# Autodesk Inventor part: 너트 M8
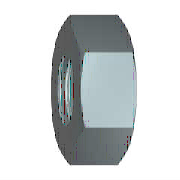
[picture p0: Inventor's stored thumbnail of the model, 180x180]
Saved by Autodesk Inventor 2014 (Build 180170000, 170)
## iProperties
IsCustomPart: 1
Created: 2012-02
Part Number: 너트 M8
Material: 강철, 연강
Description: 6각 너트
Document SubType Name: Modeling
Standard: KS B 1012
Designer: mduedu
Standards Organization: KS
Language: ko-KR
Size Designation: M8
Categories: <MemberInstance><Categories><Category DisplayName="조임쇠" InternalName="e4da775c-781d-43d5-af7c-5136215cf5a6" Mnemonic="FSTN"><Category DisplayName="너트" InternalN
Density: 1 g/cm^3
Appearance: Steel
Author: mduedu
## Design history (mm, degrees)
sketch "스케치1"
  geometry: L1 (-7.506, 0)-(-3.753, 6.5); L2 (-3.753, 6.5)-(3.753, 6.5); L3 (3.753, 6.5)-(7.506, 0); L4 (7.506, 0)-(3.753, -6.5); L5 (3.753, -6.5)-(-3.753, -6.5); L6 (-3.753, -6.5)-(-7.506, 0); 2 further points
  constraints: 12 end point, 1 coincident, 1 horizontal, 11 other
  dimensions: "d0" = 15.01111 distance of L3.end L1.start (= 1.1547 x SW)
extrude "본체" new body sketch "스케치1" distance "d1" = 5 (= KOH); taper "d2" = 0 deg
sketch "스케치2"
  geometry: L1 (0, 3.753)-(0, 7.506) reference; L2 (0, 7.506)-(5, 7.506) reference; L3 (5, 3.753)-(5, 7.506) reference; L4 (-1, 0)-(6, 0) reference; L5 (0.581, 7.506)-(0, 6.5); L6 (4.419, 7.506)-(5, 6.5)
  constraints: 4 end point, 4 point on line
  dimensions: "d3" = 30 deg angle of L1 L5 (= ANG1); "d4" = 30 deg angle of L3 L6 (= ANG2); "d5" = 13 diameter of L5.end L4 (= SW0); "d6" = 13 diameter of L6.end L4 (= SW01)
revolve "모따기1" sketch "스케치2" stored, may be unused: angle "d7" = 90 deg
sketch "스케치3"
  geometry: A1 r 6.5 centre (0, 0) between (-3.25, -5.629) and (3.25, -5.629) reference; 1 further point
  constraints: 1 coincident
hole "스레드" sketch "스케치3" at (0, 0) diameter "d25" = 6.647; stored, may be unused: countersink angle "d29" = 82 deg, drill point angle "d31" = 118 deg; dims "d26" = 6, "d27" = 4, "d28" = 2, "d30" = 8
workaxis "Work Axis1"
workplane "Work Plane1"
body "Solid1"
chamfer "모따기2" distance "d8" = 0.67658 (= -0.5 x GD1 + 0.5 x NND); stored, may be unused: angle "d9" = 30 deg, second distance "d40" = 0.67658 (= -0.5 x GD1 + 0.5 x NND)
chamfer "모따기3" distance "d10" = 0.67658 (= -0.5 x GD1 + 0.5 x NND); stored, may be unused: angle "d11" = 30 deg, second distance "d41" = 0.67658 (= -0.5 x GD1 + 0.5 x NND)
other parameters: "ANG1" = 30 deg [user parameter; used in 1 equation term], "ANG2" = 30 deg [user parameter; used in 1 equation term], "NND" = 8 [user parameter; used in 4 equation terms], "KOH" = 5 [user parameter; used in 1 equation term], "SW" = 13 [user parameter; used in 4 equation terms], "SW0" = 13 (= SW) [user parameter; used in 1 equation term], "SW01" = 13 (= SW) [user parameter; used in 1 equation term], "GD1" = 6.64684 (computed from THREADDIA, PTC, TOA) [user parameter; used in 4 equation terms], "d13" = 0, "d14" = 0, "d39" = 0, "d42" = 0, "GUL" = 0.67658 (= 0.541266 x PTC) [user parameter], "TPU" = 8 (computed from PTC) [user parameter], "THREADDIA" = 8 [user parameter; used in 1 equation term], "TOA" = 30 deg [user parameter; used in 1 equation term], "PTC" = 1.25 [user parameter; used in 4 equation terms], "E0" = 15.015 (= 1.155 x SW) [user parameter], "GAL" = 0.67658 (= 0.541266 x PTC) [user parameter]
